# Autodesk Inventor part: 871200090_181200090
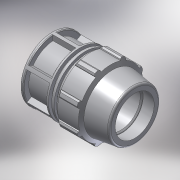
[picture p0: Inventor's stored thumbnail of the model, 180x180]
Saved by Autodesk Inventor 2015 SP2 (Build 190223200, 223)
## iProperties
Created: 2017-02
Part Number: 871200090_181200090
Material: PVC-Piping
Description: PLASSON END PLUG 90
Document SubType Name: Modeling
Designer: KIM
Mass: 92.6774 g
Surface Area: 199.44 cm^2
Volume: 66.1981 cm^3
Density: 1.4 g/cm^3
Appearance: Smooth - White
Author: Кирилл
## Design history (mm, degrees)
derived "87120.ipt"
feature "Solid1::87120.ipt"
tag "TaggingFeature1"
body "Solid1"
other parameters: "d4" = 30.14286, "d5" = 52.75, "d7" = 152, "d8" = 114, "d9" = 30.14286, "d11" = 6.02857, "d12" = 121.6, "d13" = 120 deg, "d14" = 117, "d15" = 8 deg, "d16" = 136.8, "d18" = 4.5, "d19" = 35 deg, "d20" = 17.5 deg, "d21" = 141.36, "d23" = 0, "d25" = 360 deg, "d27" = 3.04, "d34" = 7.6, "d36" = 0, "d42" = 52.75, "d43" = 4.56, "d46" = 2.7, "d53" = 1.8, "d55" = 360 deg, "d59" = 52.75, "d64" = 211, "d66" = 19.76, "d67" = 12.16, "d68" = 169, "d70" = 24.11429, "d71" = 6.02857, "d72" = 134.064, "d75" = 12.05714, "E_" = 152, "H_" = 211, "l_" = 169
